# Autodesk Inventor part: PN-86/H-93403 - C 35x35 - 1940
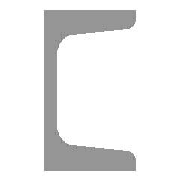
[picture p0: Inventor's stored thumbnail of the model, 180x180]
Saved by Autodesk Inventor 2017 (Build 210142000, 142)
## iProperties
_CCFamilyMember: 10
_CCFamilyDisplayName: PN-86/H-93403 - Ceownik
_FrameMemberDoc: Frame Member File
_Version: 15.0.0
_GetPNFromCC: 1
Created: 2016-02
Part Number: PN-86/H-93403 - C 35x35 - 1940
Material: Stal, miękka
Description: Ceownik
Document SubType Name: Modeling
Standard: PN
Designer: X
Standards Organization: PN
Language: pl-PL
Size Designation: C 35x35
Categories: <MemberInstance><Categories><Category DisplayName="Kształtowniki konstrukcyjne" InternalName="089c4875-fa83-4c05-b084-43b9cc11f5ed" Mnemonic="GRDR"><CategoryPar
Stock Number: C 35x35
Density: 7.85 g/cm^3
Appearance: Częściowo polerowana
IsCustomPart: 1
G_L: 1940,000 mm
G_W: 35,000 mm
G_H: 35,000 mm
Author: X
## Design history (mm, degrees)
node "Płaszczyzna początkowa"
node "Płaszczyzna końcowa"
sketch "Szkic"
  geometry: L1 (0, 0)-(0, 17.5); L2 (0, 17.5)-(35, 17.5); L3 (35, 17.5)-(35, 15.47); L4 (32.239, 12.479)-(10.522, 10.742); L5 (5, 4.761)-(5, 0); L6 (5, 0)-(0, 0); L7 (20, 17.5)-(20, 11.5); L8 (35, 12.7)-(35, 11.5); L9 (35, 11.5)-(20, 11.5); L10 (0, 15)-(0, -27); L11 (-5.539, 0)-(16.007, 0); L12 (0, 0)-(0, -17.5); L13 (0, -17.5)-(35, -17.5); L14 (35, -17.5)-(35, -15.47); L15 (32.239, -12.479)-(10.522, -10.742); L16 (5, -4.761)-(5, 0); L17 (0, 26.4)-(0, -35.9) reference; L18 (-13.764, 0)-(43.809, 0) reference; A1 r 6 centre (11, 4.761) between (10.522, 10.742) and (5, 4.761); A2 r 6 centre (11, -4.761) between (5, -4.761) and (10.522, -10.742); A3 r 3 centre (32, 15.47) between (32.239, 12.479) and (35, 15.47); A4 r 3 centre (32, -15.47) between (35, -15.47) and (32.239, -12.479); 5 further points
  constraints: 32 end point, 12 point on line, 8 point on circle, 8 tangent, 6 symmetric about line, 4 centre point, 4 parallel, 3 collinear, 3 perpendicular, 2 equal radius, 5 other
  dimensions: "d0" = 5 distance between parallel lines of L1 L5 (= G_T); "d1" = 17.5 distance between parallel lines of L6 L2 (= 0.5 x G_H); "d2" = 35 distance between parallel lines of L3 L1 (= G_W); "d3" = 6 distance of L2.end L8.end (= G_T1); "d4" = 15 distance of L7.start L2.end (= G_C); "d5" = 1.2 distance of L8.start L8.end (computed from G_NG, G_C); "d23" = 6 radius of A1 (= G_IR); "d24" = 3 radius of A3 (= G_ER); "d25" = 0 distance between parallel lines of L10 L12 (computed from ex)
extrude "Bryła" new body sketch "Szkic" stored distance "d6" = 1940 (= G_L); taper "d7" = 0 deg
node "Driven Length"
  sketch "Sketch3"
    geometry: L1 (0, 0)-(10, 0) reference
    constraints: 2 end point, 1 horizontal
  workplane "Work Plane3"
  sketch "Sketch4"
    geometry: L1 (-2, 0)-(12, 0) reference; L2 (-2, 1940)-(12, 1940) reference
    dimensions: "d29" = 1940 distance between parallel lines of L1 L2 (derived)
body "Solid1"
other parameters: "G_W" = 35 [user parameter; used in 1 equation term], "G_H" = 35 [user parameter; used in 1 equation term], "G_T" = 5 [user parameter; used in 1 equation term], "G_T1" = 6 [user parameter; used in 1 equation term], "G_NG" = 0.8 [user parameter; used in 1 equation term], "G_ER" = 3 [user parameter; used in 1 equation term], "G_IR" = 6 [user parameter; used in 1 equation term], "G_C" = 15 [user parameter; used in 2 equation terms], "G_L" = 1940 (= d29) [user parameter; used in 1 equation term], "ex" = 0 [user parameter; used in 1 equation term], "G_OFFSET_START" = 0 [user parameter; used in 1 equation term], "G_OFFSET_END" = 0 [user parameter; used in 1 equation term], "d26" = 0 (computed from G_OFFSET_START), "d28" = 90 deg
